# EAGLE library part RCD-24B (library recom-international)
DC/DC-Converter Constant Current Output, Power LED Driver Source: http://www.recom-international.de/pdf/Innoline/RCD-24B.pdf
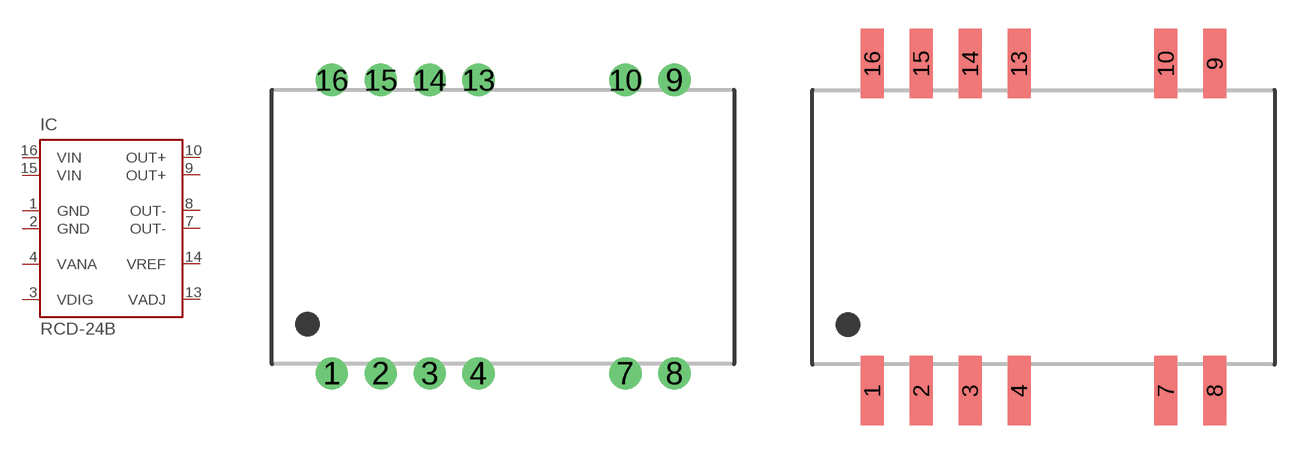
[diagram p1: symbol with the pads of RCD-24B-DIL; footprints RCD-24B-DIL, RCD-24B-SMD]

Designator prefix IC

## RCD-24B-0.70 (OC_FARNELL: unknown; OC_NEWARK: unknown)  [RCD-24B-DIL]
1  GND  pwr
2  GND  pwr
3  VDIG  pas
4  VANA  pas
7  OUT-  out
8  OUT-  out
9  OUT+  out
10  OUT+  out
13  VADJ  pas
14  VREF  in
15  VIN  in
16  VIN  in

## RCD-24B-0.70/SMD (OC_FARNELL: unknown; OC_NEWARK: unknown)  [RCD-24B-SMD]
Pads as for RCD-24B-DIL

## Footprint RCD-24B-DIL (pad centres in mm)
DC/DC Converter RCD.24 Series Through Hole Case Style Source: http://www.recom-international.de/pdf/Innoline/RCD-24B.pdf
drill 1 pad 1.676 round: 1 -8.89,-7.62; 2 -6.35,-7.62; 3 -3.81,-7.62; 4 -1.27,-7.62; 7 6.35,-7.62; 8 8.89,-7.62; 9 8.89,7.62; 10 6.35,7.62; 13 -1.27,7.62; 14 -3.81,7.62; 15 -6.35,7.62; 16 -8.89,7.62

## Footprint RCD-24B-SMD (pad centres in mm)
DC/DC Converter RCD.24 Series SMD Case Style Source: http://www.recom-international.de/pdf/Innoline/RCD-24B.pdf
smd 1.2 x 3.6: 1 -8.89,-8.495; 2 -6.35,-8.495; 3 -3.81,-8.495; 4 -1.27,-8.495; 7 6.35,-8.495; 8 8.89,-8.495; 9 8.89,8.495; 10 6.35,8.495; 13 -1.27,8.495; 14 -3.81,8.495; 15 -6.35,8.495; 16 -8.89,8.495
